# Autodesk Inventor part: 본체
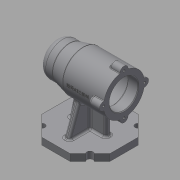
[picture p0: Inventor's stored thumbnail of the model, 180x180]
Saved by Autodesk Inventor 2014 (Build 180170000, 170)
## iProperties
Created: 2021-01
Part Number: 본체
Material: Generic
Document SubType Name: Modeling
Designer: kh
Density: 1 g/cm^3
Appearance: Default
Author: kh
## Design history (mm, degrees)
sketch "Sketch1" dims "d0" = 100
  geometry: L1 (20.711, 50)-(50, 20.711); L2 (50, 20.711)-(50, -20.711); L3 (50, -20.711)-(20.711, -50); L4 (20.711, -50)-(-20.711, -50); L5 (-20.711, -50)-(-50, -20.711); L6 (-50, -20.711)-(-50, 20.711); L7 (-50, 20.711)-(-20.711, 50); L8 (-20.711, 50)-(20.711, 50); 4 further points
  constraints: 16 end point, 2 coincident, 2 vertical alignment, 1 midpoint, 19 other
extrude "Extrusion1" new body sketch "Sketch1" distance "d1" = 10; taper "d2" = 0 deg
sketch "Sketch2"
  geometry: L1 (-20.711, 0)-(20.711, 0) reference; L2 (-50, 75)-(50, 75); L3 (50, 75)-(50, 105); L4 (50, 105)-(-10, 105); L5 (-10, 105)-(-30, 100); L6 (-30, 100)-(-50, 100); L7 (-50, 100)-(-50, 75); 2 further points
  constraints: 12 end point, 3 parallel, 2 perpendicular, 1 vertical alignment
  dimensions: "d3" = 75 distance from line of L2 point (0, 0); "d4" = 60 diameter of L4 L2; "d5" = 100 distance between parallel lines of L7 L3; "d6" = 20 distance of L5.end L6.end; "d7" = 40 horizontal distance of L4.end L6.end; "d8" = 50 diameter of L6 L2
revolve "Revolution1" sketch "Sketch2" stored, may be unused: angle "d9" = 90 deg
sketch "Sketch3"
  geometry: L1 (-50, 50)-(-50, 100) reference; L2 (50, 45)-(50, 105) reference; L3 (-20.711, 0)-(20.711, 0) reference; L4 (-50, 75)-(50, 75); L5 (50, 75)-(35, 75); L6 (35, 75)-(35, 96); L7 (35, 96)-(50, 96); L8 (50, 96)-(50, 75); L9 (35, 75)-(-7, 75); L10 (-7, 75)-(-7, 99); L11 (-7, 99)-(35, 99); L12 (35, 99)-(35, 75); L13 (-7, 75)-(-19, 75); L14 (-19, 75)-(-19, 96); L15 (-19, 96)-(-7, 96); L16 (-7, 96)-(-7, 75); L17 (-19, 75)-(-37, 75); L18 (-37, 75)-(-37, 92.5); L19 (-37, 92.5)-(-19, 92.5); L20 (-19, 92.5)-(-19, 75); L21 (-37, 75)-(-41, 75); L22 (-41, 75)-(-41, 91); L23 (-41, 91)-(-37, 91); L24 (-37, 91)-(-37, 75); L25 (-41, 75)-(-44, 75); L26 (-44, 75)-(-44, 85.5); L27 (-44, 85.5)-(-41, 85.5); L28 (-41, 85.5)-(-41, 75); 1 further point
  constraints: 50 end point, 12 parallel, 6 horizontal, 6 perpendicular, 2 midpoint
  dimensions: "d10" = 42 diameter of L7 L4; "d11" = 48 diameter of L11 L9; "d12" = 42 diameter of L15 L4; "d13" = 35 diameter of L19 L4; "d14" = 32 diameter of L23 L4; "d15" = 21 diameter of L27 L4; "d16" = 3 distance of L26.end L27.end; "d17" = 4 distance of L22.end L23.end; "d18" = 18 distance of L18.end L19.end; "d19" = 12 distance of L14.end L15.end; "d21" = 15 distance of L6.end L7.end; "d22" = 42 distance of L10.end L11.end
revolve "Revolution2" sketch "Sketch3" stored, may be unused: angle "d23" = 90 deg
sketch "Sketch4"
  geometry: L1 (50, 45)-(50, 105) reference; L2 (50, 10)-(20.711, 10) reference; L3 (27, 10)-(27, 40.084); 1 further point
  constraints: 2 end point, 1 perpendicular, 1 point on line
  dimensions: "d24" = 23 distance from line of L3 L2.start
feature "Rib1" sketch "Sketch4" dims "d25" = 1, "d26" = 8, "d27" = 0, "d28" = 0, "d29" = 1, "d30" = 1
sketch "Sketch5"
  geometry: L1 (-50, 0)-(-50, 10) reference; L2 (20.711, 10)-(-20.711, 10) reference; L3 (-20.711, 10)-(-50, 10) reference; L4 (-27, 10)-(-20.637, 42.737); 1 further point
  constraints: 2 end point, 1 point on line
  dimensions: "d31" = 23 distance of L4.start L1.end; "d32" = 101 deg angle of L3 L4
feature "Rib2" sketch "Sketch5" dims "d33" = 1, "d34" = 8, "d35" = 0, "d36" = 0, "d37" = 1, "d38" = 1
sketch "Sketch6"
  geometry: L1 (50, 0)-(50, 10) reference; L2 (50, 10)-(20.711, 10) reference; L3 (35, 10)-(22.377, 44.681); 1 further point
  constraints: 2 end point, 1 point on line
  dimensions: "d39" = 15 distance from line of L3.start L1; "d40" = 110 deg angle of L2 L3
feature "Rib3" sketch "Sketch6" dims "d41" = 1, "d42" = 8, "d43" = 0, "d44" = 0, "d45" = 1, "d46" = 1
mirror "Mirror1"
fillet "Fillet1" dims "d47" = 10
sketch "Sketch7"
  geometry: C1 r 6 at (0, -30); 2 further points
  constraints: 2 vertical alignment, 1 centre point, 1 other
  dimensions: "d48" = 12 diameter of C1
extrude "Extrusion2" join sketch "Sketch7" distance "d49" = 16; taper "d50" = 0 deg
hole "Hole1" diameter "d53" = 3.242; stored, may be unused: countersink angle "d57" = 90 deg, drill point angle "d59" = 118 deg; dims "d51" = 10, "d52" = 10, "d54" = 8, "d55" = 4, "d56" = 2, "d58" = 10
pattern_circular "Circular Pattern1" dims angle "d61" = 360 deg
sketch "Sketch8"
  geometry: L1 (-50, -20.711)-(-50, 20.711) reference; L2 (-50, 20.711)-(-20.711, 50) reference; L3 (-20.711, 50)-(20.711, 50) reference; L4 (20.711, 50)-(50, 20.711) reference; L5 (50, 20.711)-(50, -20.711) reference; L6 (50, -20.711)-(20.711, -50) reference; L7 (20.711, -50)-(-20.711, -50) reference; L8 (-20.711, -50)-(-50, -20.711) reference; L9 (-50, 0)-(50, 0); L10 (0, 0)-(-35.355, 35.355); 1 further point
  constraints: 4 end point, 3 midpoint, 1 coincident
hole "Hole2" sketch "Sketch8" at (-35.355, 35.355) diameter "d63" = 9; stored, may be unused: countersink angle "d67" = 90 deg, drill point angle "d69" = 118 deg; dims "d64" = 8, "d65" = 4, "d66" = 2, "d68" = 10
pattern_circular "Circular Pattern2" dims angle "d71" = 360 deg
fillet "Fillet2" dims "d73" = 3
fillet "Fillet3" dims "d74" = 3
fillet "Fillet4" dims "d75" = 3
fillet "Fillet5" dims "d76" = 0.3
fillet "Fillet6" dims "d77" = 3
fillet "Fillet7" dims "d78" = 3
fillet "Fillet8" dims "d79" = 3
fillet "Fillet9" dims "d80" = 1
fillet "Fillet10" dims "d81" = 3
fillet "Fillet11" dims "d82" = 1
workplane "Work Plane1"
sketch "Sketch9"
  geometry: L1 (30, 5.998)-(30, -5.998) reference; L2 (30, 36)-(30, 30.171) reference; L3 (-24.592, 2.402)-(8.592, 2.402); L4 (8.592, 2.402)-(8.592, -2.402); L5 (8.592, -2.402)-(-24.592, -2.402); L6 (-24.592, -2.402)-(-24.592, 2.402); L7 (-24.592, -2.402)-(8.592, 2.402); 3 further points
  constraints: 2 end point, 2 midpoint, 1 horizontal alignment, 2 other
  dimensions: "d83" = 38 distance from line of L2 point (-8, 0)
emboss "Emboss1" sketch "Sketch9" dims "d0" = 100, "d3" = 75, "d4" = 60, "d5" = 100, "d6" = 20, "d7" = 40, "d8" = 50, "d84" = 0.5, "d85" = 0
fillet "Fillet12" dims "d86" = 3
chamfer "Chamfer1" distance "d87" = 1; stored, may be unused: second distance "d88" = 2, angle "d89" = 45 deg
body "Solid1"
node "Projected Loop1"
